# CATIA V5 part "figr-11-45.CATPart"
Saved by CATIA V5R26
Part number: Part1
Bounding box of the stored display mesh (mm): x -59 to 59, y -60 to 210, z -30 to 39.8
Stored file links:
  D:\_Deepak\CATIA\CATIA V5-6R2016_Deepak\Resources\Part files\Partfiles\c11_catia_v5_6r2016_prt\figr-11-45.CATPart
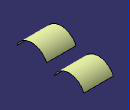
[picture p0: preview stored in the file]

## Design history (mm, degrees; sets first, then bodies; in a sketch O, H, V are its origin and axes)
AxisSystem1: origin (0, 0, 0), X (1, 0, 0), Y (0, 1, 0), Z (0, 0, 1)
AxisSystem2: origin (0, 150, -30), X (1, 0, 0), Y (0, 1, 0), Z (0, 0, 1)
Set1
  Extrude1: Element1 Sketch2, Lim1 59, Lim2 59, Direction yz-plane
  Sketch1 on yz-plane, origin (0, 0, 0), H (0, 1, 0), V (0, 0, 1)
    point P1 (150, -30)
  AxisToAxis1: ToTransfor Extrude1, AxisOrigin AxisSystem1, Axis AxisSystem2
Body1 (main body)
  Sketch2 on yz-plane, origin (0, 0, 0), H (0, 1, 0), V (0, 0, 1)
    arc A1 centre (0, -25) radius 65 from (-60, 0) to (60, 0) cw
    point P2 (-60, 0)
    point P3 (60, 0)
    coincidence: P2 H, P3 H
